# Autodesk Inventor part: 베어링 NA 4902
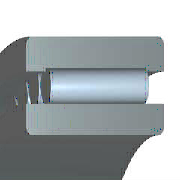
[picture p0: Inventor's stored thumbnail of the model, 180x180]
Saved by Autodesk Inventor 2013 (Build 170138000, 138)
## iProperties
IsCustomPart: 1
Created: 2012-02
Part Number: 베어링 NA 4902
Material: 강철, 연강
Description: 니들 롤러 베어링 - 경계 치수 및 공차
Document SubType Name: Modeling
Standard: KS B 2029
Designer: mduedu
Standards Organization: KS
Language: ko-KR
Size Designation: NA 4902 - 15 x 28 x 13
Categories: <MemberInstance><Categories><Category DisplayName="샤프트 부품" InternalName="7f7aeb1f-a693-4053-b835-cee3144e0d98" Mnemonic="SHFT"><Category DisplayName="베어링" Inter
Density: 1 g/cm^3
Author: mduedu
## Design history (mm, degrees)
sketch "스케치"
  geometry: L1 (1.857, 11.5)-(11.143, 11.5); L2 (11.143, 11.5)-(11.143, 10); L3 (13, 10)-(0, 10); L4 (1.857, 10)-(1.857, 11.5); L5 (1.857, 10.75)-(11.143, 10.75); L6 (6.5, 10.75)-(6.5, 10); L7 (0, 7.5)-(13, 7.5); L8 (0, 14)-(13, 14); L9 (13, 7.5)-(13, 10); L10 (13, 11.35)-(13, 14); L11 (1.857, 11.35)-(0, 11.35); L12 (11.143, 11.35)-(13, 11.35); L13 (-6, 0)-(36, 0) reference; L14 (0, -1.9)-(0, 14.9) reference
  constraints: 24 end point, 8 point on line, 3 midpoint, 3 parallel, 3 perpendicular, 2 symmetric about line, 1 horizontal, 1 other
  dimensions: "d6" = 15 diameter of L7 L13 (= WD); "d7" = 20 diameter of L3 L13 (= KID1); "d8" = 28 diameter of L8 L13 (= BD); "d9" = 21.5 diameter of L6.start L13 (= 0.5 x WD + 0.5 x BD); "d10" = 22.7 diameter of L12 L13 (= 0.9 x BD + 0.9 x WD - 0.8 x KID1); "d11" = 23 diameter of L1 L13 (= BD + WD - KID1); "d12" = 1.85714 distance between parallel lines of L14 L4 (= 0.142857 x KB); "d13" = 13 distance between parallel lines of L14 L9 (= KB); "d14" = 11.14286 distance between parallel lines of L14 L2 (= 0.857143 x KB)
revolve "본체" stored, may be unused: angle "d17" = 90 deg
revolve "롤러" stored, may be unused: angle "d18" = 90 deg
node "작업 평면1"
body "Solid1"
fillet "모깎기1" dims "d0" = 0.3 (= KRS)
pattern_circular "IDS_ARRAYROLLER[SIMPL:T]" dims angle "d2" = 360 deg
other parameters: "WD" = 15 [user parameter; used in 6 equation terms], "BD" = 28 [user parameter; used in 6 equation terms], "KB" = 13 [user parameter; used in 3 equation terms], "KID1" = 20 [user parameter; used in 4 equation terms], "KRS" = 0.3 [user parameter; used in 1 equation term], "d3" = 0, "d4" = 0, "d5" = 0, "d15" = 0, "d16" = 0, "BC0" = 1.37e+07 [user parameter], "WR" = 7.5 (= 0.5 x WD) [user parameter], "BBA" = 0 [user parameter], "BC" = 1.02e+07 [user parameter], "BR" = 14 (= 0.5 x BD) [user parameter]
